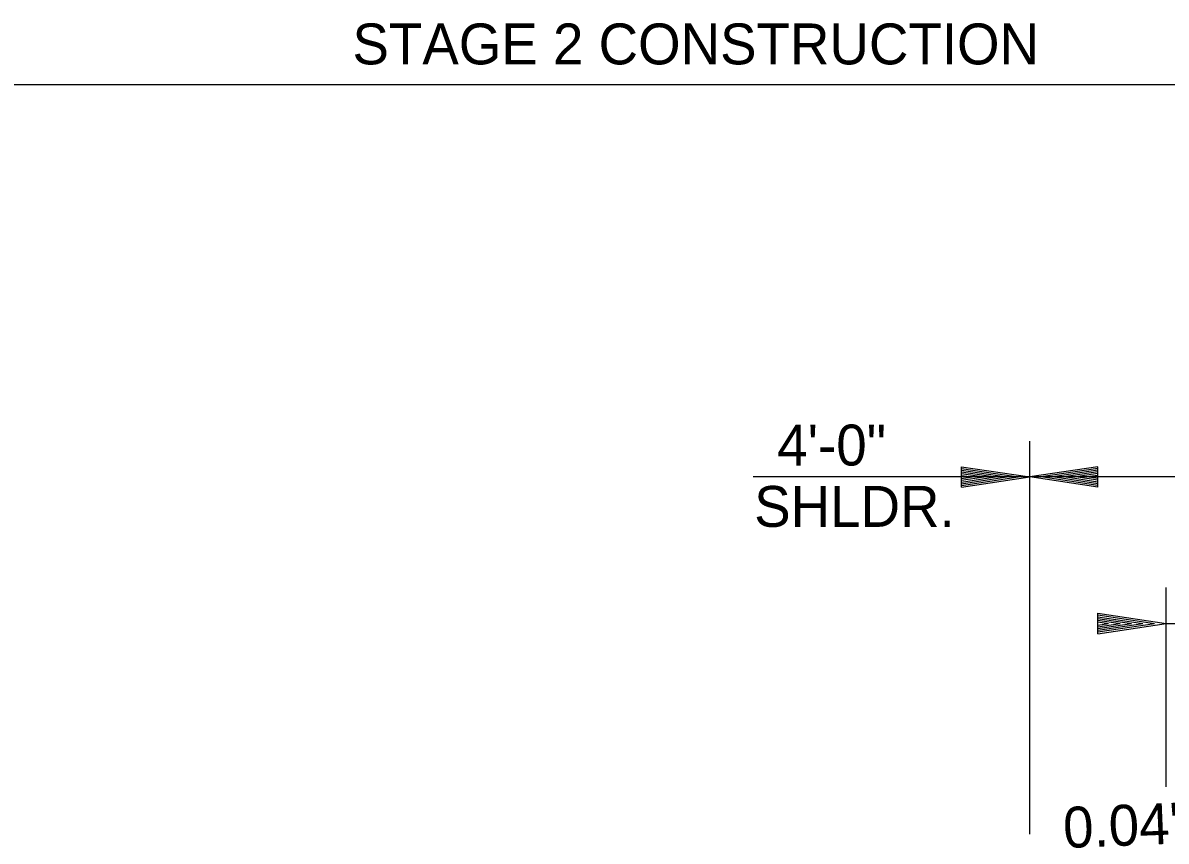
# Model space of a CAD drawing. Extents: x 2829243 to 2838161, y 467639 to 474695.
# Drawn here: x 2829953 to 2830120.8, y 472901 to 473021.1 of the extents above; entities that cross this region are included whole.
import ezdxf

# ---------------------------------------------------------------- set-up
doc = ezdxf.new("R2010")
doc.units = 0
doc.layers.add('R_Dimension', color=7, linetype='Continuous')
doc.layers.add('R_Draft', color=7, linetype='Continuous')

msp = doc.modelspace()

# ---------------------------------------------------------------- linework, layer by layer
at = {"layer": 'R_Dimension'}
for p, q in [((2830400.77, 473011.97), (2829709.86, 473011.97)), ((2830100.77, 472902.05), (2830100.77, 472959.69)), ((2830090.77, 472955.94), (2830100.77, 472954.44)), ((2830090.77, 472952.94), (2830090.77, 472955.94)), ((2830090.77, 472955.69), (2830099.1, 472954.44)), ((2830090.77, 472955.44), (2830097.38, 472954.44)), ((2830090.77, 472955.19), (2830095.72, 472954.44)), ((2830090.77, 472954.93), (2830094.02, 472954.44)), ((2830110.77, 472955.94), (2830100.77, 472954.44)), ((2830110.77, 472955.69), (2830102.44, 472954.44)), ((2830110.77, 472955.44), (2830104.16, 472954.44)), ((2830110.77, 472955.19), (2830105.83, 472954.44)), ((2830110.77, 472954.93), (2830107.52, 472954.44)), ((2830110.77, 472952.94), (2830110.77, 472955.94)), ((2830100.77, 472954.44), (2830060.2, 472954.44)), ((2830090.77, 472954.68), (2830092.35, 472954.44)), ((2830090.77, 472952.94), (2830100.77, 472954.44)), ((2830090.77, 472953.96), (2830094.02, 472954.44)), ((2830090.77, 472953.45), (2830097.38, 472954.44)), ((2830090.77, 472953.19), (2830099.1, 472954.44)), ((2830090.77, 472953.7), (2830095.72, 472954.44)), ((2830090.77, 472954.21), (2830092.35, 472954.44)), ((2830140.77, 472954.44), (2830100.77, 472954.44)), ((2830110.77, 472952.94), (2830100.77, 472954.44)), ((2830110.77, 472953.19), (2830102.44, 472954.44)), ((2830110.77, 472953.45), (2830104.16, 472954.44)), ((2830110.77, 472953.7), (2830105.83, 472954.44)), ((2830110.77, 472953.96), (2830107.52, 472954.44)), ((2830110.77, 472954.68), (2830109.19, 472954.44)), ((2830110.77, 472954.21), (2830109.19, 472954.44)), ((2830120.77, 472908.96), (2830120.77, 472938.2))]:
    msp.add_line(p, q, dxfattribs=at)
at = {"layer": 'R_Draft'}
for p, q in [((2830110.77, 472934.45), (2830120.77, 472932.95)), ((2830110.77, 472931.45), (2830110.77, 472934.45)), ((2830110.77, 472934.2), (2830119.1, 472932.95)), ((2830110.77, 472933.94), (2830117.38, 472932.95)), ((2830110.77, 472933.69), (2830115.72, 472932.95)), ((2830110.77, 472933.44), (2830114.02, 472932.95)), ((2830110.77, 472933.18), (2830112.35, 472932.95)), ((2830110.77, 472931.45), (2830120.77, 472932.95)), ((2830110.77, 472932.46), (2830114.02, 472932.95)), ((2830110.77, 472931.95), (2830117.38, 472932.95)), ((2830110.77, 472931.7), (2830119.1, 472932.95)), ((2830110.77, 472932.2), (2830115.72, 472932.95)), ((2830110.77, 472932.71), (2830112.35, 472932.95)), ((2830120.77, 472932.95), (2830180.99, 472932.95))]:
    msp.add_line(p, q, dxfattribs=at)

# ---------------------------------------------------------------- texts
at = {"layer": 'R_Dimension'}
for s, p in [('STAGE 2 CONSTRUCTION', (2830001.39, 473014.97)), ('4\'-0"', (2830063.72, 472956.12)), ('SHLDR.', (2830060.34, 472947.12))]:
    msp.add_text(s, height=6, dxfattribs=at).set_placement(p)
at = {"layer": 'R_Draft'}
msp.add_text("0.04'/'", height=6, rotation=2.2906, dxfattribs=at).set_placement((2830105.79, 472899.99))

doc.saveas('drawing.dxf')
